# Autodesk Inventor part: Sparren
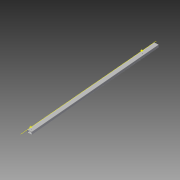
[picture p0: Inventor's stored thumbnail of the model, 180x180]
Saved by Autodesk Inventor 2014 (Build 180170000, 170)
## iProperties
Created: 2013-09
Part Number: Sparren
Material: Stahl
Document SubType Name: Modeling
Designer: Stefan Tammegger
Mass: 31427.8 g
Surface Area: 20041.8 cm^2
Volume: 4003.54 cm^3
Density: 7.85 g/cm^3
Appearance: Stahl
Author: Stefan Tammegger
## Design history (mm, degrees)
node "Blöcke"
  sketch "FR 100_60_4"
    geometry: L1 (25.014, 27.2)-(-66.986, 27.2); L2 (-70.986, 31.2)-(-70.986, 83.2); L3 (-66.986, 87.2)-(25.014, 87.2); L4 (29.014, 83.2)-(29.014, 31.2); L5 (25.014, 31.2)-(-66.986, 31.2); L6 (-66.986, 31.2)-(-66.986, 83.2); L7 (-66.986, 83.2)-(25.014, 83.2); L8 (25.014, 83.2)-(25.014, 31.2); A1 r 4 centre (25.014, 31.2) between (25.014, 27.2) and (29.014, 31.2); A2 r 4 centre (25.014, 83.2) between (29.014, 83.2) and (25.014, 87.2); A3 r 4 centre (-66.986, 83.2) between (-66.986, 87.2) and (-70.986, 83.2); A4 r 4 centre (-66.986, 31.2) between (-70.986, 31.2) and (-66.986, 27.2); 4 further points
    constraints: 16 end point, 8 point on circle, 8 tangent, 6 point on line, 4 centre point, 4 parallel, 3 equal radius, 2 perpendicular, 1 horizontal, 1 midpoint, 3 other
    dimensions: "d2" = 100 distance of point (-70.986, 87.2) point (29.014, 87.2); "d3" = 60 distance of point (-70.986, 27.2) point (-70.986, 87.2); "d4" = 4 distance between parallel lines of L4 L8; "d5" = 4 radius of A1
workpoint "Arbeitspunkt1"
workplane "Arbeitsebene1"
  workaxis "Arbeitsachse1"
sketch "Skizze1"
  geometry: L1 (-155.058, 0)-(-3.636, 0) reference; L2 (0, 0)-(0, -3809.707) reference; 1 further point
  constraints: 1 other
extrude "Extrusion1" new body sketch "Skizze1" distance "d6" = 3000; taper "d8" = 0 deg; dims "d7" = 330, "d9" = 0
sketch "Skizze2"
  geometry: C1 r 7 at (47.653, 2959.343) reference; C2 r 7 at (47.653, 48.266) reference; 1 further point
hole "Bohrung1" sketch "Skizze2" at (47.653, 48.266), (47.653, 2959.343) diameter "d10" = 14; stored, may be unused: countersink angle "d14" = 90 deg, drill point angle "d16" = 118 deg; dims "d11" = 6, "d12" = 4, "d13" = 2, "d15" = 8
sketch "Skizze3"
  geometry: C1 r 3 at (26, 3280) reference; C2 r 4.75 at (26, 2820) reference; C3 r 4.703 at (26, 2360) reference; C4 r 4.75 at (26, 1900) reference; C5 r 4.703 at (26, 1440) reference; C6 r 4.703 at (26, 980) reference; C7 r 4.75 at (26, 520) reference; C8 r 4.703 at (26, 60) reference; 1 further point
hole "Bohrung2" sketch "Skizze3" at (26, 3280), (26, 2820), (26, 2360), (26, 1900), (26, 1440), (26, 980), (26, 520), (26, 60) diameter "d17" = 4.134; stored, may be unused: countersink angle "d21" = 90 deg, drill point angle "d23" = 118 deg; dims "d18" = 6, "d19" = 4, "d20" = 2, "d22" = 8
node "Volumenkörper1"
workpoint "Arbeitspunkt2"
node "Referenz1"
node "Referenz2"
node "Referenz3"
node "Referenz4"
node "Referenz5"
node "Referenz6"
node "Referenz7"
node "Referenz8"
node "Referenz9"
node "Referenz10"
node "Referenz11"
node "Referenz12"
node "FR 100_60_4:1"
